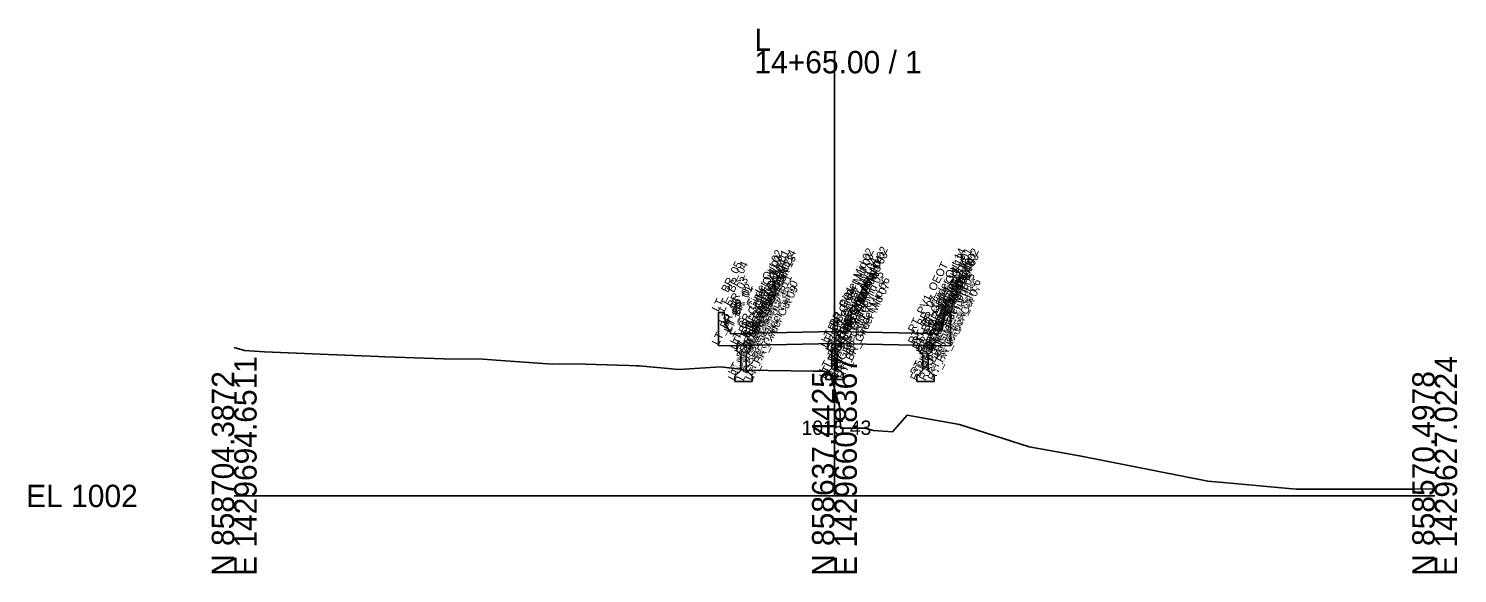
# Model space of a CAD drawing. Extents: x -26 to 2303, y -10 to 19558.
# Drawn here: x 1124.3 to 1302.8, y 19490.3 to 19558.5 of the extents above; entities that cross this region are included whole.
import ezdxf

# ---------------------------------------------------------------- set-up
doc = ezdxf.new("R2010")
doc.units = 0
for name, color, linetype in [('Default', 7, 'Continuous'), ('Exist Cross Section Cell', 7, 'Continuous'), ('Exist XS Center Line Elevation Label', 7, 'Continuous'), ('Exist XS Ground Line', 7, 'Continuous'), ('Prop CMT Concrete Structures', 7, 'Continuous'), ('Prop XS Dump Level', 7, 'Continuous')]:
    doc.layers.add(name, color=color, linetype=linetype)

msp = doc.modelspace()

# ---------------------------------------------------------------- linework, layer by layer
at = {"layer": 'Exist Cross Section Cell'}
for p, q in [((1225, 19500), (1225, 19555.65)), ((1150, 19500), (1225, 19500)), ((1225, 19500), (1300, 19500))]:
    msp.add_line(p, q, dxfattribs=at)
at = {"layer": 'Exist XS Ground Line'}
msp.add_lwpolyline([(1150, 19518.55), (1151.29, 19518.19), (1152.52, 19518.1), (1153.79, 19518.04), (1161.78, 19517.7), (1168.01, 19517.45), (1168.83, 19517.39), (1170.11, 19517.36), (1176.2, 19517.15), (1181.12, 19517.09), (1182.72, 19516.97), (1189.73, 19516.49), (1192.5, 19516.52), (1199.3, 19516.33), (1200.27, 19516.28), (1200.59, 19516.29), (1205.56, 19515.81), (1206.27, 19515.84), (1210.76, 19516.13), (1212.53, 19515.93), (1213.25, 19515.84), (1213.9, 19515.74), (1222.37, 19515.62), (1223.74, 19515.59), (1224.09, 19515.58), (1224.4, 19515.54), (1225, 19513.43), (1225.68, 19511.02), (1225.75, 19508.49), (1228.79, 19508.48), (1229.88, 19508.17), (1232.26, 19508.03), (1234.1, 19510.12), (1240.62, 19508.92), (1249.35, 19506.15), (1255.6, 19505.02), (1271.64, 19501.83), (1274.01, 19501.65), (1282.7, 19500.86), (1297.47, 19500.83), (1300, 19500.87)], dxfattribs=at)
at = {"layer": 'Prop CMT Concrete Structures'}
for points in [[(1225, 19520.55), (1215, 19520.35), (1212, 19520.29), (1211.99, 19520.54), (1211.41, 19521.37), (1211.24, 19522.96), (1210.5, 19522.96), (1210.5, 19518.76)], [(1225, 19520.55), (1235, 19520.35), (1238, 19520.29), (1238.01, 19520.54), (1238.59, 19521.37), (1238.76, 19522.96), (1239.5, 19522.96), (1239.5, 19518.76)], [(1210.5, 19518.76), (1215, 19518.85), (1225, 19519.05)], [(1225, 19519.05), (1224.17, 19519.03)], [(1224.17, 19519.03), (1224.17, 19518.38)], [(1225, 19519.05), (1225, 19520.55)], [(1225, 19519.05), (1225, 19520.55)], [(1225, 19514.55), (1225, 19519.05)], [(1225, 19519.05), (1225.83, 19519.03)], [(1225, 19514.55), (1225, 19519.05)], [(1239.5, 19518.76), (1235, 19518.85), (1225, 19519.05)], [(1225.83, 19519.03), (1225.83, 19518.38)], [(1214.46, 19518.84), (1213.62, 19518.82), (1212.79, 19518.81)], [(1212.79, 19518.81), (1212.79, 19518.16)], [(1212.79, 19518.16), (1213.29, 19517.66)], [(1213.29, 19517.66), (1213.29, 19515.74)], [(1213.96, 19517.66), (1214.46, 19518.16)], [(1213.96, 19515.74), (1213.96, 19517.66)], [(1214.46, 19518.16), (1214.46, 19518.84)], [(1224.17, 19518.38), (1224.67, 19517.88)], [(1224.67, 19517.88), (1224.67, 19515.97)], [(1225.83, 19518.38), (1225.33, 19517.88)], [(1225.33, 19517.88), (1225.33, 19515.97)], [(1235.54, 19518.84), (1236.38, 19518.82), (1237.21, 19518.81)], [(1235.54, 19518.16), (1235.54, 19518.84)], [(1236.04, 19517.66), (1235.54, 19518.16)], [(1236.04, 19515.74), (1236.04, 19517.66)], [(1237.21, 19518.16), (1236.71, 19517.66)], [(1236.71, 19517.66), (1236.71, 19515.74)], [(1237.21, 19518.81), (1237.21, 19518.16)], [(1213.29, 19515.74), (1212.54, 19514.99)], [(1214.71, 19514.99), (1213.96, 19515.74)], [(1224.67, 19515.97), (1223.92, 19515.22)], [(1225.33, 19515.97), (1226.08, 19515.22)], [(1235.29, 19514.99), (1236.04, 19515.74)], [(1236.71, 19515.74), (1237.46, 19514.99)], [(1212.54, 19514.99), (1212.54, 19514.32)], [(1212.54, 19514.32), (1213.62, 19514.32), (1214.71, 19514.32)], [(1214.71, 19514.32), (1214.71, 19514.99)], [(1223.92, 19515.22), (1223.92, 19514.55)], [(1223.92, 19514.55), (1225, 19514.55)], [(1226.08, 19514.55), (1225, 19514.55)], [(1226.08, 19515.22), (1226.08, 19514.55)], [(1235.29, 19514.32), (1235.29, 19514.99)], [(1237.46, 19514.32), (1236.38, 19514.32), (1235.29, 19514.32)], [(1237.46, 19514.99), (1237.46, 19514.32)]]:
    msp.add_lwpolyline(points, dxfattribs=at)

# ---------------------------------------------------------------- texts
at = {"layer": 'Default'}
msp.add_text('-', height=0.0001, dxfattribs=at).set_placement((1150, 19500))
at = {"layer": 'Exist Cross Section Cell'}
for s, p in [('L', (1215, 19555.65)), ('14+65.00 / 1', (1215, 19552.85)), ('EL 1002', (1124, 19498.6))]:
    msp.add_text(s, height=2.8, dxfattribs=at).set_placement(p)
for s, p in [('E 1429694.6511', (1152.8, 19490)), ('E 1429660.8367', (1227.8, 19490)), ('E 1429627.0224', (1302.8, 19490)), ('N 858704.3872', (1150, 19490)), ('N 858637.4425', (1225, 19490)), ('N 858570.4978', (1300, 19490))]:
    msp.add_text(s, height=2.8, rotation=90, dxfattribs=at).set_placement(p)
at = {"layer": 'Exist XS Center Line Elevation Label'}
msp.add_text('1015.43', height=1.8, dxfattribs=at).set_placement((1220.9, 19507.63))
at = {"layer": 'Prop XS Dump Level'}
for s, p in [('LT_BR_Girder Out 02', (1212.79, 19518.81)), ('LT_BR_Girder Out 03', (1212.79, 19518.16)), ('LT_BR_Girder Out 01', (1213.62, 19518.82)), ('LT_BR_Girder Out 14', (1214.46, 19518.84)), ('LT_BR_Girder Out 13', (1214.46, 19518.16)), ('LT_BR_Girder Mid 02', (1224.17, 19519.03)), ('LT_BR_Girder Mid 03', (1224.17, 19518.38)), ('LT_BR_Girder Mid 04', (1224.67, 19517.88)), ('RT_BR_Girder Mid 04', (1225.33, 19517.88)), ('RT_BR_Girder Mid 02', (1225.83, 19519.03)), ('RT_BR_Girder Mid 03', (1225.83, 19518.38)), ('RT_BR_Girder Out 14', (1235.54, 19518.84)), ('RT_BR_Girder Out 13', (1235.54, 19518.16)), ('RT_BR_Girder Out 12', (1236.04, 19517.66)), ('RT_BR_Girder Out 01', (1236.38, 19518.82)), ('RT_BR_Girder Out 04', (1236.71, 19517.66)), ('RT_BR_Girder Out 02', (1237.21, 19518.81)), ('RT_BR_Girder Out 03', (1237.21, 19518.16)), ('LT_ BR_05', (1210.5, 19522.96)), ('LT_ BR_04', (1211.24, 19522.96)), ('LT_BR_Girder Out 04', (1213.29, 19517.66)), ('LT_BR_Girder Out 12', (1213.96, 19517.66)), ('LT_PV1_OEOT', (1215, 19520.35)), ('LT_BR_Girder Mid 05', (1224.67, 19515.97)), ('RT_BR_Girder Mid 05', (1225.33, 19515.97)), ('RT_PV1_OEOT', (1235, 19520.35)), ('RT_BR_Girder Out 05', (1236.71, 19515.74)), ('RT_ BR_04', (1238.76, 19522.96)), ('RT_ BR_05', (1239.5, 19522.96)), ('LT_BR_03', (1211.41, 19521.37)), ('LT_BR_02', (1211.99, 19520.54)), ('LT_BR_01', (1212, 19520.29)), ('LT_BR_Girder Out 06', (1212.54, 19514.99)), ('LT_BR_Girder Out 07', (1212.54, 19514.32)), ('LT_BR_Girder Out 05', (1213.29, 19515.74)), ('LT_BR_Girder Out 08', (1213.62, 19514.32)), ('LT_BR_Girder Out 11', (1213.96, 19515.74)), ('LT_BR_Girder Out 10', (1214.71, 19514.99)), ('LT_BR_Girder Out 09', (1214.71, 19514.32)), ('LT_BR_Girder Mid 06', (1223.92, 19515.22)), ('LT_BR_Girder Mid 07', (1223.92, 19514.55)), ('RT_BR_Girder Mid 06', (1226.08, 19515.22)), ('RT_BR_Girder Mid 07', (1226.08, 19514.55)), ('RT_BR_Girder Out 10', (1235.29, 19514.99)), ('RT_BR_Girder Out 09', (1235.29, 19514.32)), ('RT_BR_Girder Out 11', (1236.04, 19515.74)), ('RT_BR_Girder Out 08', (1236.38, 19514.32)), ('RT_BR_Girder Out 06', (1237.46, 19514.99)), ('RT_BR_Girder Out 07', (1237.46, 19514.32)), ('RT_BR_01', (1238, 19520.29)), ('RT_BR_02', (1238.01, 19520.54)), ('RT_BR_03', (1238.59, 19521.37)), ('LT_BR_06', (1210.5, 19518.76)), ('LT_BR_07', (1215, 19518.85)), ('PV1_PGL', (1225, 19520.55)), ('BR_Girder Mid 08', (1225, 19514.55)), ('RT_BR_07', (1235, 19518.85)), ('RT_BR_06', (1239.5, 19518.76)), ('BR_PGL', (1225, 19519.05))]:
    msp.add_text(s, height=1, rotation=63.5833, dxfattribs=at).set_placement(p)

doc.saveas('drawing.dxf')
